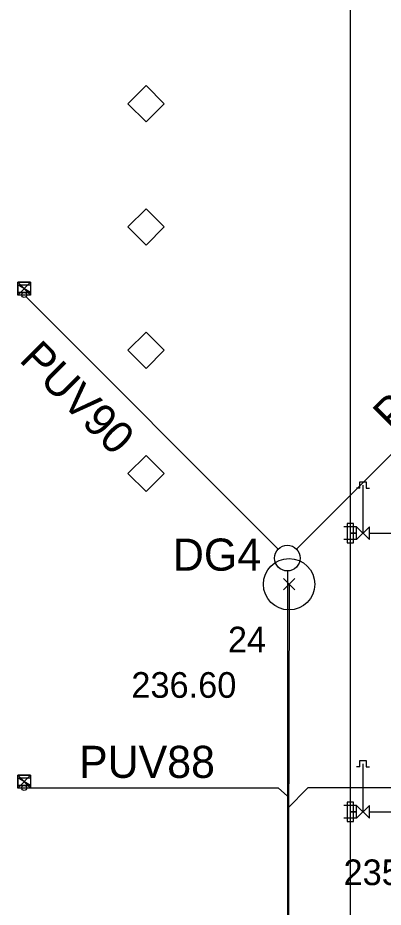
# Model space of a CAD drawing. Extents: x -264234 to -263604, y -1242346 to -1242049.
# Drawn here: x -263937.09 to -263922.86, y -1242121 to -1242086.36 of the extents above; entities that cross this region are included whole.
import ezdxf

# ---------------------------------------------------------------- set-up
doc = ezdxf.new("R2010")
doc.units = 0
for name, color, linetype in [('KFA_BODY_CISLO', 7, 'Continuous'), ('KFA_BODY_SYMBOL', 7, 'Continuous'), ('KFA_BODY_VYSKA', 7, 'Continuous'), ('KFA_DAZDOVA_KANALIZACIA_vetva_G', 7, 'Continuous'), ('KFA_DAZDOVA_KANALIZACIA_vetva_G_popis', 7, 'Continuous'), ('KFA_SITUACIA_DSP', 7, 'Continuous'), ('KFA_SO_40-2-II_DK_PRIPOJKY_UV_PROJEKT', 7, 'Continuous'), ('KFA_SO_40-2-II_DK_PRIPOJKY_UV_PROJEKT_popis', 7, 'Continuous'), ('KFA_SO_40-2-II_DK_UV_PROJEKT', 7, 'Continuous')]:
    doc.layers.add(name, color=color, linetype=linetype)

msp = doc.modelspace()

# ---------------------------------------------------------------- linework, layer by layer
at = {"layer": 'KFA_BODY_SYMBOL'}
for p, q in [((-263926.744, -1242108.641), (-263926.302, -1242108.199)), ((-263926.302, -1242108.641), (-263926.744, -1242108.199))]:
    msp.add_line(p, q, dxfattribs=at)
at = {"layer": 'KFA_DAZDOVA_KANALIZACIA_vetva_G'}
msp.add_lwpolyline([(-263926.523, -1242108.42), (-263926.639, -1242155.082), (-263926.646, -1242205.066)], dxfattribs=at)
msp.add_circle((-263926.523, -1242108.42), 1, dxfattribs=at)
at = {"layer": 'KFA_SITUACIA_DSP'}
for p, q in [((-263924.143, -1242082.64), (-263924.143, -1242185.14)), ((-263932.8, -1242089.707), (-263932.093, -1242089)), ((-263932.093, -1242089), (-263931.386, -1242089.707)), ((-263932.093, -1242089), (-263932.093, -1242089)), ((-263932.093, -1242090.414), (-263932.8, -1242089.707)), ((-263931.386, -1242089.707), (-263932.093, -1242090.414)), ((-263932.8, -1242094.507), (-263932.093, -1242093.8)), ((-263932.093, -1242093.8), (-263931.386, -1242094.507)), ((-263932.093, -1242093.8), (-263932.093, -1242093.8)), ((-263932.093, -1242095.214), (-263932.8, -1242094.507)), ((-263931.386, -1242094.507), (-263932.093, -1242095.214)), ((-263937.093, -1242097.052), (-263937.093, -1242096.762)), ((-263937.093, -1242096.762), (-263936.593, -1242096.762)), ((-263936.593, -1242097.052), (-263937.093, -1242096.762)), ((-263936.593, -1242097.052), (-263937.093, -1242096.762)), ((-263937.093, -1242096.762), (-263937.093, -1242097.052)), ((-263936.593, -1242096.762), (-263936.593, -1242097.052)), ((-263936.593, -1242097.052), (-263937.093, -1242097.052)), ((-263937.093, -1242097.052), (-263936.593, -1242097.052)), ((-263936.772, -1242097.223), (-263926.946, -1242107.049)), ((-263916.414, -1242097.223), (-263926.239, -1242107.049)), ((-263932.8, -1242099.307), (-263932.093, -1242098.6)), ((-263932.093, -1242098.6), (-263931.386, -1242099.307)), ((-263932.093, -1242098.6), (-263932.093, -1242098.6)), ((-263932.093, -1242100.014), (-263932.8, -1242099.307)), ((-263931.386, -1242099.307), (-263932.093, -1242100.014)), ((-263932.8, -1242104.107), (-263932.093, -1242103.4)), ((-263932.093, -1242103.4), (-263931.386, -1242104.107)), ((-263932.093, -1242103.4), (-263932.093, -1242103.4)), ((-263932.093, -1242104.814), (-263932.8, -1242104.107)), ((-263931.386, -1242104.107), (-263932.093, -1242104.814)), ((-263923.768, -1242104.682), (-263923.768, -1242104.432)), ((-263923.768, -1242104.432), (-263923.518, -1242104.432)), ((-263923.518, -1242104.432), (-263923.518, -1242104.682)), ((-263923.768, -1242104.682), (-263923.893, -1242104.682)), ((-263923.643, -1242106.432), (-263923.643, -1242104.557)), ((-263923.518, -1242104.682), (-263923.393, -1242104.682)), ((-263923.893, -1242106.182), (-263924.393, -1242106.182)), ((-263924.018, -1242106.057), (-263924.268, -1242106.057)), ((-263924.268, -1242106.057), (-263924.268, -1242106.807)), ((-263924.018, -1242106.807), (-263924.018, -1242106.057)), ((-263923.893, -1242106.682), (-263923.893, -1242106.182)), ((-263923.893, -1242106.182), (-263923.393, -1242106.682)), ((-263923.393, -1242106.182), (-263923.893, -1242106.682)), ((-263923.393, -1242106.682), (-263923.393, -1242106.182)), ((-263924.143, -1242106.432), (-263923.893, -1242106.432)), ((-263923.893, -1242106.432), (-263924.143, -1242106.432)), ((-263923.393, -1242106.432), (-263903.343, -1242106.432)), ((-263923.893, -1242106.682), (-263924.393, -1242106.682)), ((-263924.268, -1242106.807), (-263924.018, -1242106.807)), ((-263926.593, -1242107.902), (-263926.593, -1242154.252)), ((-263926.593, -1242107.902), (-263926.593, -1242154.252)), ((-263923.768, -1242115.532), (-263923.893, -1242115.532)), ((-263923.768, -1242115.532), (-263923.768, -1242115.282)), ((-263923.768, -1242115.282), (-263923.518, -1242115.282)), ((-263923.643, -1242117.282), (-263923.643, -1242115.407)), ((-263923.518, -1242115.282), (-263923.518, -1242115.532)), ((-263923.518, -1242115.532), (-263923.393, -1242115.532)), ((-263937.093, -1242116.252), (-263937.093, -1242115.962)), ((-263937.093, -1242115.962), (-263936.593, -1242115.962)), ((-263936.593, -1242116.252), (-263937.093, -1242115.962)), ((-263936.593, -1242116.252), (-263937.093, -1242115.962)), ((-263937.093, -1242115.962), (-263937.093, -1242116.252)), ((-263936.593, -1242116.252), (-263937.093, -1242116.252)), ((-263937.093, -1242116.252), (-263936.593, -1242116.252)), ((-263936.593, -1242115.962), (-263936.593, -1242116.252)), ((-263936.743, -1242116.352), (-263926.953, -1242116.352)), ((-263926.953, -1242116.352), (-263926.592, -1242116.677)), ((-263925.797, -1242116.352), (-263926.592, -1242117.147)), ((-263916.443, -1242116.352), (-263925.797, -1242116.352)), ((-263924.018, -1242116.907), (-263924.268, -1242116.907)), ((-263924.268, -1242116.907), (-263924.268, -1242117.657)), ((-263924.018, -1242117.657), (-263924.018, -1242116.907)), ((-263923.893, -1242117.032), (-263924.393, -1242117.032)), ((-263924.143, -1242117.282), (-263923.893, -1242117.282)), ((-263923.893, -1242117.282), (-263924.143, -1242117.282)), ((-263923.893, -1242117.532), (-263923.893, -1242117.032)), ((-263923.893, -1242117.032), (-263923.393, -1242117.532)), ((-263923.393, -1242117.032), (-263923.893, -1242117.532)), ((-263923.393, -1242117.532), (-263923.393, -1242117.032)), ((-263923.393, -1242117.282), (-263906.493, -1242117.282)), ((-263923.893, -1242117.532), (-263924.393, -1242117.532)), ((-263924.268, -1242117.657), (-263924.018, -1242117.657))]:
    msp.add_line(p, q, dxfattribs=at)
for centre, radius in [((-263936.843, -1242097.152), 0.1), ((-263926.593, -1242107.402), 0.5), ((-263936.843, -1242116.352), 0.1)]:
    msp.add_circle(centre, radius, dxfattribs=at)
at = {"layer": 'KFA_SO_40-2-II_DK_PRIPOJKY_UV_PROJEKT'}
for points in [[(-263936.772, -1242097.223), (-263926.946, -1242107.049)], [(-263916.414, -1242097.223), (-263926.239, -1242107.049)], [(-263936.743, -1242116.352), (-263926.953, -1242116.352), (-263926.592, -1242116.677)], [(-263916.443, -1242116.352), (-263925.797, -1242116.352), (-263926.592, -1242117.147)]]:
    msp.add_lwpolyline(points, dxfattribs=at)
at = {"layer": 'KFA_SO_40-2-II_DK_UV_PROJEKT'}
for points in [[(-263937.093, -1242097.157), (-263937.093, -1242096.657), (-263936.593, -1242096.657), (-263936.593, -1242097.157), (-263937.093, -1242097.157), (-263936.593, -1242096.657), (-263937.093, -1242096.657), (-263936.593, -1242097.157)], [(-263937.093, -1242116.357), (-263937.093, -1242115.857), (-263936.593, -1242115.857), (-263936.593, -1242116.357), (-263937.093, -1242116.357), (-263936.593, -1242115.857), (-263937.093, -1242115.857), (-263936.593, -1242116.357)]]:
    msp.add_lwpolyline(points, dxfattribs=at)

# ---------------------------------------------------------------- texts
at = {"layer": 'KFA_BODY_CISLO'}
msp.add_text('24', height=1, dxfattribs=at).set_placement((-263928.907, -1242111.073))
at = {"layer": 'KFA_BODY_VYSKA'}
for s, p in [('236.60', (-263932.669, -1242112.842)), ('235.27', (-263924.404, -1242120.137))]:
    msp.add_text(s, height=1, dxfattribs=at).set_placement(p)
at = {"layer": 'KFA_DAZDOVA_KANALIZACIA_vetva_G_popis'}
msp.add_text('DG4', height=1.25, dxfattribs=at).set_placement((-263931.05, -1242107.891))
at = {"layer": 'KFA_SO_40-2-II_DK_PRIPOJKY_UV_PROJEKT_popis'}
for s, rotation, p in [('PUV91', 45, (-263922.479, -1242102.529)), ('PUV90', 315, (-263937.074, -1242099.714))]:
    msp.add_text(s, height=1.25, rotation=rotation, dxfattribs=at).set_placement(p)
msp.add_text('PUV88', height=1.25, dxfattribs=at).set_placement((-263934.709, -1242115.961))

doc.saveas('drawing.dxf')
